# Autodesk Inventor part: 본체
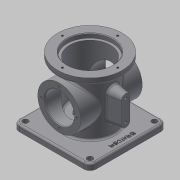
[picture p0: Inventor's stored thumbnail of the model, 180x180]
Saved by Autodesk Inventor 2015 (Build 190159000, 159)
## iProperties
Created: 2017-08
Part Number: 본체
Material: 일반
Document SubType Name: Modeling
Designer: mduedu
Density: 2.71 g/cm^3
Mass: 872.327 g
Surface Area: 642.238 cm^2
Volume: 321.892 cm^3
Appearance: 기본값
Author: mduedu
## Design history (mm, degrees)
sketch "스케치1"
  geometry: L1 (-62.5, -62.5)-(62.5, -62.5); L2 (62.5, -62.5)-(62.5, 62.5); L3 (62.5, 62.5)-(-62.5, 62.5); L4 (-62.5, 62.5)-(-62.5, -62.5); L5 (-62.5, -62.5)-(62.5, 62.5); L6 (62.5, -62.5)-(-62.5, 62.5); 1 further point
  constraints: 12 end point, 2 midpoint, 2 parallel, 1 horizontal, 1 perpendicular
  dimensions: "d232" = 125 distance of L3.end L2.end; "d233" = 125 distance of L2.end L1.end
extrude "돌출1" new body sketch "스케치1" distance "d5" = 10; taper "d6" = 0 deg
sketch "스케치2"
  geometry: C1 r 38 at (0, 0); 1 further point
  constraints: 1 centre point, 1 coincident
  dimensions: "d111" = 76 diameter of C1
extrude "돌출2" join sketch "스케치2" distance "d12" = 88; taper "d13" = 0 deg
sketch "스케치3"
  geometry: C1 r 52.5 at (0, 0); 1 further point
  constraints: 1 centre point, 1 coincident
  dimensions: "d114" = 105 diameter of C1
extrude "돌출3" join sketch "스케치3" distance "d19" = 10; taper "d20" = 0 deg
sketch "스케치4"
  geometry: C1 r 33 at (0, 0); 1 further point
  constraints: 1 centre point, 1 coincident
  dimensions: "d115" = 66 diameter of C1
extrude "돌출4" cut sketch "스케치4" distance "d26" = 86; taper "d27" = 0 deg
sketch "스케치5"
  geometry: C1 r 37 at (0, 0); 1 further point
  constraints: 1 centre point, 1 coincident
  dimensions: "d116" = 74 diameter of C1
extrude "돌출5" cut sketch "스케치5" distance "d29" = 7; taper "d30" = 0 deg
node "작업 평면1"
sketch "스케치18"
  geometry: L1 (-62.5, 0)-(62.5, 0) reference; C1 r 35 at (0, 54); 1 further point
  constraints: 1 centre point, 1 vertical alignment
  dimensions: "d118" = 70 diameter of C1; "d234" = 54 distance from line of C1.centre L1
extrude "돌출9" join sketch "스케치18" stored distance "d120" = 10; taper "d121" = 0 deg
hole "구멍8" diameter "d124" = 48; stored, may be unused: countersink angle "d128" = 90 deg, drill point angle "d130" = 118 deg; dims "d122" = 10, "d123" = 10, "d125" = 6, "d126" = 4, "d127" = 2, "d129" = 8
sketch "스케치9"
  geometry: C1 r 33 at (0, 0); 1 further point
  constraints: 1 centre point, 1 coincident
  dimensions: "d131" = 66 diameter of C1
extrude "돌출8" cut sketch "스케치9" distance "d43" = 16; taper "d44" = 0 deg
node "작업 평면2"
fillet "모깎기9" dims "d137" = 3
fillet "모깎기10" dims "d138" = 3
chamfer "모따기2" distance "d139" = 1; stored, may be unused: second distance "d140" = 2, angle "d141" = 45 deg
fillet "모깎기11" dims "d142" = 3
fillet "모깎기12" dims "d143" = 3
fillet "모깎기13" dims "d144" = 3
node "작업 평면3"
sketch "스케치20"
  geometry: L1 (108, -52.5)-(108, 52.5) reference; L2 (37, 7)-(71, 7); L3 (37, -7)-(71, -7); L4 (0, -33)-(0, 33) reference; A1 r 7 centre (37, 0) between (37, 7) and (37, -7); A2 r 7 centre (71, 0) between (71, 7) and (71, -7); 1 further point
  constraints: 4 end point, 4 point on circle, 3 tangent, 2 centre point, 2 horizontal alignment, 1 parallel, 1 perpendicular
  dimensions: "d203" = 14 diameter of A1; "d206" = 30 distance edge to line of A2 L1; "d207" = 48 dimension on A2 A1 (derived); "d236" = 30 distance edge to line of A1 L4
extrude "돌출10" join sketch "스케치20" stored distance "d152" = 10; taper "d153" = 10 deg
sketch "스케치21"
  geometry: C1 r 7 at (0, 71) reference; C2 r 7 at (0, 37) reference; 3 further points
  constraints: 2 coincident
hole "구멍12" sketch "스케치21" at (0, 71), (0, 37) diameter "d219" = 4.134; stored, may be unused: countersink angle "d223" = 90 deg, drill point angle "d225" = 118 deg; dims "d220" = 6, "d221" = 4, "d222" = 2, "d224" = 8
fillet "모깎기18" dims "d229" = 3
sketch "스케치23"
  geometry: C1 r 20 at (0, 0); 1 further point
  constraints: 1 centre point, 1 coincident
  dimensions: "d168" = 40 diameter of C1
extrude "돌출12" cut sketch "스케치23" stored distance "d169" = 148.25; taper "d170" = 0 deg
sketch "스케치28"
  geometry: L1 (62.5, -62.5)-(62.5, 62.5) reference; 2 further points
  constraints: 1 horizontal alignment, 1 other
  dimensions: "d238" = 10 distance from line of point (52.5, 0) L1
feature "엠보싱4" sketch "스케치28" dims "d239" = 0.5, "d240" = 0
sketch "스케치25" dims "d178" = 58
  geometry: C1 r 35 at (0, 0) reference; 3 further points
  constraints: 2 vertical alignment, 1 coincident, 2 other
hole "구멍10" sketch "스케치25" at (0, 29) diameter "d179" = 3.242; stored, may be unused: countersink angle "d183" = 90 deg, drill point angle "d185" = 118 deg; dims "d180" = 4, "d181" = 4, "d182" = 2, "d184" = 6
sketch "스케치26" dims "d189" = 90
  geometry: 3 further points
  constraints: 2 vertical alignment, 1 coincident, 2 other
hole "구멍11" sketch "스케치26" at (0, 45) diameter "d190" = 3.242; stored, may be unused: countersink angle "d194" = 90 deg, drill point angle "d196" = 118 deg; dims "d191" = 4, "d192" = 4, "d193" = 2, "d195" = 6
chamfer "모따기4" distance "d200" = 1; stored, may be unused: second distance "d201" = 2, angle "d202" = 45 deg
fillet "모깎기19" dims "d241" = 10
sketch "스케치29"
  geometry: A1 r 10 centre (-52.5, 52.5) between (-52.5, 62.5) and (-62.5, 52.5) reference; A2 r 10 centre (52.5, 52.5) between (62.5, 52.5) and (52.5, 62.5) reference; A3 r 10 centre (52.5, -52.5) between (52.5, -62.5) and (62.5, -52.5) reference; A4 r 10 centre (-52.5, -52.5) between (-62.5, -52.5) and (-52.5, -62.5) reference; 5 further points
  constraints: 4 coincident
hole "구멍13" sketch "스케치29" at (-52.5, 52.5), (52.5, 52.5), (52.5, -52.5), (-52.5, -52.5) diameter "d242" = 9; stored, may be unused: countersink angle "d246" = 90 deg, drill point angle "d248" = 118 deg; dims "d243" = 6, "d244" = 4, "d245" = 2, "d247" = 8
fillet "모깎기20" dims "d249" = 3
node "솔리드1"
mirror "대칭2"
pattern_circular "원형 패턴1" dims angle "d187" = 360 deg
mirror "대칭3"
pattern_circular "원형 패턴2" dims angle "d198" = 360 deg
other parameters: "d147" = 58
